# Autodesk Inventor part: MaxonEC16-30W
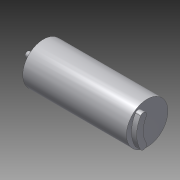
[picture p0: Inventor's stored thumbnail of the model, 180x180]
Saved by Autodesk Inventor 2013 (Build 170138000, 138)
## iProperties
Created: 2012-07
Part Number: MaxonEC16-30W
Material: Titan
Document SubType Name: Modeling
Designer: rYan
Mass: 36.7331 g
Surface Area: 25.9963 cm^2
Volume: 8.1448 cm^3
Density: 4.51 g/cm^3
Author: rYan
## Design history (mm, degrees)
sketch "Skizze1"
  geometry: L1 (-23.05, 0)-(-23.05, 1); L2 (-23.05, 1)-(-17.95, 1); L3 (-17.95, 1)-(-17.95, 4.5); L4 (-17.95, 4.5)-(-16.95, 4.5); L5 (-16.95, 4.5)-(-16.95, 8); L6 (-16.95, 8)-(23.05, 8); L7 (23.05, 8)-(23.05, 0); L8 (23.05, 0)-(-23.05, 0); L9 (0, 9.6)-(0, -1.6) reference; L10 (-32.27, 0)-(32.27, 0) reference; 1 further point
  constraints: 16 end point, 6 parallel, 1 collinear, 1 perpendicular, 1 vertical, 1 other
  dimensions: "d1" = 2 diameter of L2 L8; "d3" = 9 diameter of L4 L8; "d4" = 16 diameter of L6 L8; "d6" = 6.1 distance between parallel lines of L5 L1; "d7" = 1 distance between parallel lines of L5 L3; "d8" = 40 distance between parallel lines of L7 L5
revolve "Umdrehung1" sketch "Skizze1" stored, may be unused: angle "d9" = 90 deg
sketch "Skizze2"
  geometry: C1 r 4.5 at (0, 0) reference; 2 further points
  constraints: 1 coincident
hole "Bohrung1" sketch "Skizze2" at (0, 0) diameter "d10" = 7; stored, may be unused: countersink angle "d14" = 90 deg, drill point angle "d16" = 0 deg; dims "d11" = 6, "d12" = 4, "d13" = 2, "d15" = 0.5
sketch "Skizze3"
  geometry: L1 (-11.2, 0)-(11.2, 0) reference; L2 (0, -11.2)-(0, 11.2) reference; A1 r 8.75 centre (0, 5.2) between (-4.375, -2.378) and (4.375, -2.378); A2 r 1.25 centre (-5, -3.46) between (-4.375, -2.378) and (-5.625, -4.543); A3 r 1.25 centre (5, -3.46) between (5.625, -4.543) and (4.375, -2.378); A4 r 11.25 centre (0, 5.2) between (-5.625, -4.543) and (5.625, -4.543)
  constraints: 8 point on circle, 4 centre point, 4 tangent, 1 point on line, 1 symmetric about line
  dimensions: "d19" = 8.75 radius of A1; "d20" = 11.25 radius of A4; "d21" = 5.2 distance from line of L1 A1.centre; "d22" = 10 distance of A3.centre A2.centre; "d23" = 1.25 radius of A3
extrude "Extrusion1" join sketch "Skizze3" distance "d24" = 2; taper "d25" = 0 deg
sketch "Skizze4" dims "d26" = 11
  geometry: L1 (-11.2, 0)-(11.2, 0) reference; L2 (0, 11.2)-(0, -11.2) reference; C1 r 8 at (0, 0) reference; 3 further points
  constraints: 1 coincident, 1 point on line, 1 vertical alignment, 2 other
hole "Bohrung2" sketch "Skizze4" at (0, 5.5) diameter "d28" = 1.567; stored, may be unused: countersink angle "d32" = 90 deg, drill point angle "d34" = 0 deg; dims "d29" = 6, "d30" = 4, "d31" = 2, "d33" = 3.5
pattern_circular "Runde Anordnung1" dims angle "d36" = 360 deg
node "Volumenkörper1"
